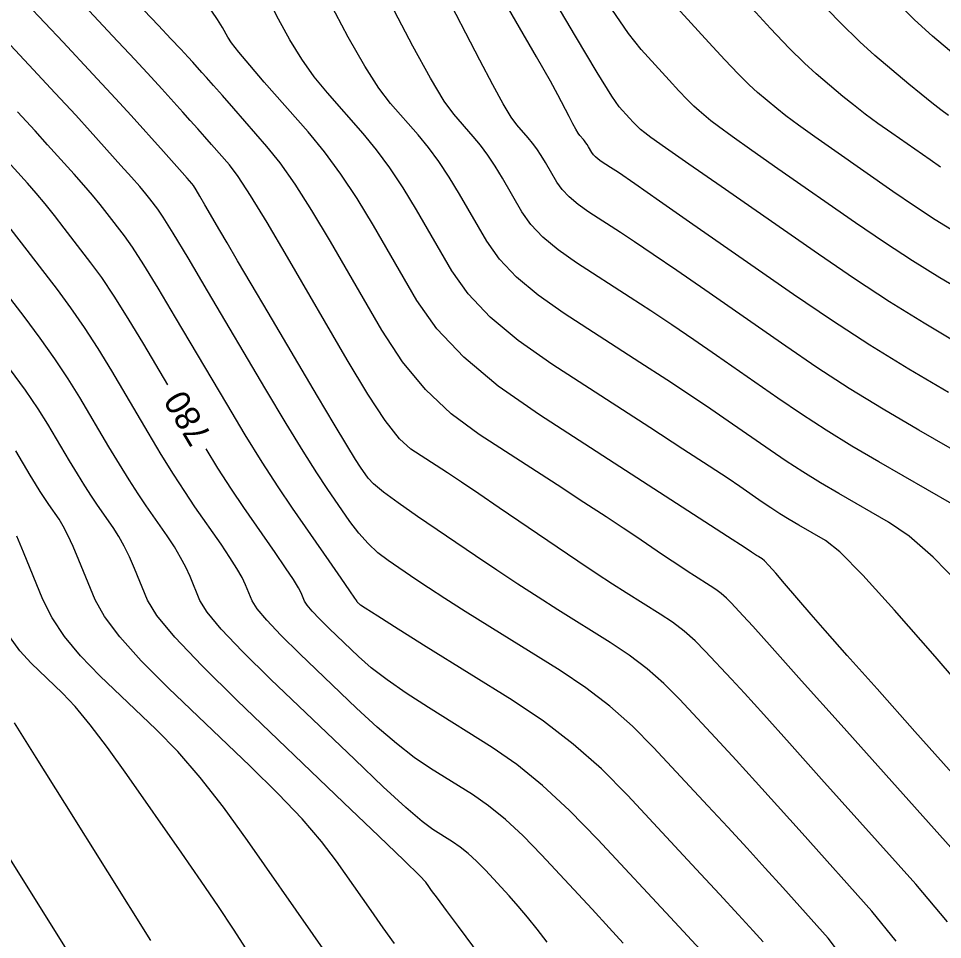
# Model space of a CAD drawing. Extents: x 2082232 to 2083549, y 592624 to 593832.
# Drawn here: x 2082485.39 to 2082511.4, y 593238.65 to 593264.58 of the extents above; entities that cross this region are included whole.
import ezdxf

# ---------------------------------------------------------------- set-up
doc = ezdxf.new("R2010")
doc.units = 0
doc.layers.add('DT_X_Contour_Major', color=7, linetype='Continuous')
doc.layers.add('DT_X_Contour_Minor', color=7, linetype='Continuous')

msp = doc.modelspace()

# ---------------------------------------------------------------- linework, layer by layer
at = {"layer": 'DT_X_Contour_Major'}
for points in [[(2082511.88, 593240.97), (2082508.547, 593244.695), (2082507.437, 593245.935), (2082506.608, 593246.86), (2082506.059, 593247.469), (2082505.791, 593247.764), (2082505.451, 593248.13), (2082505.318, 593248.263), (2082505.176, 593248.388), (2082505.025, 593248.504), (2082504.864, 593248.611), (2082504.422, 593248.887), (2082504.242, 593249.001), (2082504.032, 593249.139), (2082503.793, 593249.298), (2082503.523, 593249.48), (2082502.766, 593249.996), (2082502.415, 593250.231), (2082501.929, 593250.552), (2082501.308, 593250.957), (2082500.552, 593251.447), (2082498.357, 593252.866), (2082497.568, 593253.449), (2082496.85, 593254.133), (2082496.201, 593254.918), (2082495.622, 593255.805), (2082494.171, 593258.305), (2082493.651, 593259.175), (2082493.18, 593259.911), (2082492.757, 593260.512), (2082492.383, 593260.979), (2082491.448, 593262.044), (2082491.13, 593262.407), (2082490.874, 593262.697), (2082490.682, 593262.915), (2082490.554, 593263.059), (2082490.294, 593263.348), (2082490.161, 593263.493), (2082489.956, 593263.714), (2082489.678, 593264.011), (2082489.329, 593264.382), (2082488.301, 593265.473)], [(2082513.448, 593251.436), (2082510.733, 593252.993), (2082509.736, 593253.578), (2082508.779, 593254.166), (2082507.863, 593254.757), (2082506.988, 593255.35), (2082504.709, 593256.937), (2082503.919, 593257.484), (2082503.261, 593257.937), (2082502.733, 593258.294), (2082502.335, 593258.556), (2082501.45, 593259.128), (2082501.144, 593259.342), (2082500.891, 593259.554), (2082500.692, 593259.764), (2082500.545, 593259.973), (2082500.224, 593260.526), (2082500.103, 593260.725), (2082499.983, 593260.906), (2082499.862, 593261.07), (2082499.741, 593261.217), (2082499.418, 593261.585), (2082499.262, 593261.802), (2082499.038, 593262.177), (2082498.743, 593262.71), (2082498.38, 593263.402), (2082497.318, 593265.457)], [(2082511.347, 593260.397), (2082511.053, 593260.598), (2082509.974, 593261.349), (2082509.584, 593261.625), (2082509.225, 593261.89), (2082508.897, 593262.144), (2082508.599, 593262.386), (2082507.846, 593263.018), (2082507.515, 593263.318), (2082507.086, 593263.743), (2082506.56, 593264.294), (2082505.937, 593264.971)], [(2082489.592, 593254.263), (2082488.913, 593255.41), (2082488.474, 593256.138), (2082488.08, 593256.763), (2082487.731, 593257.285), (2082487.428, 593257.703), (2082486.678, 593258.679), (2082486.402, 593259.033), (2082486.137, 593259.36), (2082485.883, 593259.663), (2082485.64, 593259.94), (2082485.008, 593260.644)], [(2082504.582, 593238.374), (2082503.869, 593239.142), (2082501.701, 593241.47), (2082500.906, 593242.287), (2082500.145, 593242.991), (2082499.419, 593243.581), (2082498.728, 593244.058), (2082496.931, 593245.18), (2082496.302, 593245.585), (2082495.765, 593245.959), (2082495.319, 593246.302), (2082494.963, 593246.614), (2082494.137, 593247.405), (2082493.861, 593247.675), (2082493.654, 593247.894), (2082493.515, 593248.06), (2082493.445, 593248.175), (2082493.347, 593248.411), (2082493.274, 593248.548), (2082493.127, 593248.782), (2082492.907, 593249.113), (2082492.612, 593249.542), (2082491.73, 593250.814), (2082491.382, 593251.329), (2082491.002, 593251.92), (2082490.668, 593252.46)], [(2082494.298, 593237.916), (2082493.683, 593238.796), (2082491.837, 593241.441), (2082491.157, 593242.379), (2082490.501, 593243.213), (2082489.87, 593243.94), (2082489.263, 593244.562), (2082487.679, 593246.078), (2082487.133, 593246.639), (2082486.684, 593247.182), (2082486.332, 593247.709), (2082486.078, 593248.22), (2082485.527, 593249.559), (2082485.34, 593250.007)]]:
    msp.add_lwpolyline(points, dxfattribs=at)
at = {"layer": 'DT_X_Contour_Minor'}
for points in [[(2082514.571, 593242.685), (2082511.197, 593246.616), (2082510.055, 593247.926), (2082509.159, 593248.908), (2082508.51, 593249.561), (2082508.106, 593249.886), (2082507.358, 593250.315), (2082507.084, 593250.476), (2082506.82, 593250.638), (2082506.568, 593250.8), (2082506.327, 593250.964), (2082505.699, 593251.401), (2082505.364, 593251.628), (2082504.83, 593251.98), (2082504.096, 593252.459), (2082503.162, 593253.064), (2082500.407, 593254.845), (2082499.456, 593255.511), (2082498.67, 593256.17), (2082498.048, 593256.824), (2082497.591, 593257.472), (2082496.592, 593259.193), (2082496.217, 593259.812), (2082495.842, 593260.376), (2082495.466, 593260.886), (2082495.09, 593261.343), (2082494.086, 593262.488), (2082493.717, 593262.939), (2082493.365, 593263.435), (2082493.028, 593263.975), (2082492.707, 593264.559), (2082491.872, 593266.175)], [(2082511.569, 593254.052), (2082510.457, 593254.706), (2082509.359, 593255.384), (2082508.276, 593256.086), (2082507.208, 593256.812), (2082504.378, 593258.782), (2082503.438, 593259.436), (2082502.738, 593259.922), (2082502.278, 593260.239), (2082502.06, 593260.387), (2082501.797, 593260.556), (2082501.707, 593260.619), (2082501.632, 593260.682), (2082501.573, 593260.745), (2082501.529, 593260.806), (2082501.434, 593260.97), (2082501.398, 593261.029), (2082501.363, 593261.083), (2082501.327, 593261.131), (2082501.291, 593261.175), (2082501.196, 593261.284), (2082501.149, 593261.348), (2082501.083, 593261.459), (2082500.996, 593261.617), (2082500.888, 593261.822), (2082500.574, 593262.431), (2082500.364, 593262.813), (2082499.971, 593263.503), (2082499.395, 593264.502), (2082498.636, 593265.809)], [(2082511.825, 593255.442), (2082510.882, 593255.999), (2082509.915, 593256.601), (2082508.923, 593257.248), (2082507.908, 593257.941), (2082505.167, 593259.848), (2082504.262, 593260.479), (2082503.603, 593260.941), (2082503.189, 593261.233), (2082503.021, 593261.356), (2082502.899, 593261.458), (2082502.845, 593261.507), (2082502.776, 593261.575), (2082502.691, 593261.665), (2082502.59, 593261.774), (2082502.3, 593262.093), (2082502.091, 593262.394), (2082501.681, 593263.056), (2082501.07, 593264.08), (2082500.258, 593265.466)], [(2082511.777, 593258.555), (2082511.201, 593258.914), (2082510.61, 593259.299), (2082510.005, 593259.712), (2082508.372, 593260.849), (2082507.81, 593261.243), (2082507.351, 593261.574), (2082506.994, 593261.84), (2082506.74, 593262.043), (2082506.197, 593262.498), (2082505.958, 593262.714), (2082505.649, 593263.021), (2082505.27, 593263.418), (2082504.822, 593263.905), (2082503.531, 593265.326)], [(2082510.098, 593238.608), (2082509.416, 593239.447), (2082507.452, 593241.641), (2082506.755, 593242.418), (2082506.136, 593243.103), (2082505.594, 593243.697), (2082505.13, 593244.199), (2082503.997, 593245.417), (2082503.557, 593245.859), (2082503.084, 593246.273), (2082502.581, 593246.659), (2082502.046, 593247.017), (2082500.577, 593247.934), (2082500.019, 593248.286), (2082499.445, 593248.657), (2082498.856, 593249.046), (2082498.252, 593249.454), (2082496.622, 593250.564), (2082496.076, 593250.943), (2082495.663, 593251.248), (2082495.383, 593251.478), (2082495.234, 593251.634), (2082495.015, 593251.949), (2082494.878, 593252.163), (2082494.631, 593252.568), (2082494.275, 593253.163), (2082493.808, 593253.949), (2082492.418, 593256.3), (2082491.942, 593257.105), (2082491.557, 593257.758), (2082491.263, 593258.259), (2082491.059, 593258.607), (2082490.639, 593259.331), (2082490.497, 593259.573), (2082490.389, 593259.754), (2082490.314, 593259.874), (2082490.272, 593259.934), (2082490.203, 593260.012), (2082490.138, 593260.085), (2082489.994, 593260.246), (2082489.771, 593260.495), (2082489.468, 593260.832), (2082488.557, 593261.846), (2082488.117, 593262.329), (2082487.48, 593263.016), (2082486.645, 593263.908), (2082485.614, 593265.003)], [(2082513.769, 593240.998), (2082510.626, 593244.511), (2082509.56, 593245.704), (2082508.718, 593246.651), (2082508.1, 593247.349), (2082507.707, 593247.801), (2082506.957, 593248.674), (2082506.706, 593248.963), (2082506.518, 593249.176), (2082506.391, 593249.311), (2082506.325, 593249.369), (2082506.233, 593249.422), (2082506.2, 593249.442), (2082506.167, 593249.462), (2082506.136, 593249.482), (2082506.107, 593249.502), (2082506.029, 593249.555), (2082505.846, 593249.675), (2082505.353, 593249.995), (2082504.55, 593250.514), (2082503.438, 593251.234), (2082500.059, 593253.418), (2082498.893, 593254.233), (2082497.929, 593255.042), (2082497.167, 593255.844), (2082496.607, 593256.639), (2082495.382, 593258.749), (2082494.922, 593259.507), (2082494.462, 593260.199), (2082494.001, 593260.825), (2082493.54, 593261.385), (2082492.308, 593262.789), (2082491.898, 593263.263), (2082491.589, 593263.631), (2082491.383, 593263.893), (2082491.278, 593264.049), (2082491.136, 593264.325), (2082490.994, 593264.549), (2082490.674, 593265.017)], [(2082511.909, 593248.631), (2082511.136, 593249.414), (2082510.462, 593250.005), (2082509.887, 593250.403), (2082508.483, 593251.207), (2082507.968, 593251.51), (2082507.473, 593251.814), (2082506.999, 593252.119), (2082506.547, 593252.426), (2082505.369, 593253.246), (2082504.883, 593253.58), (2082504.307, 593253.966), (2082503.641, 593254.404), (2082502.886, 593254.895), (2082500.754, 593256.273), (2082500.019, 593256.788), (2082499.41, 593257.298), (2082498.929, 593257.804), (2082498.576, 593258.306), (2082497.803, 593259.637), (2082497.513, 593260.116), (2082497.222, 593260.553), (2082496.931, 593260.948), (2082496.64, 593261.301), (2082495.863, 593262.187), (2082495.537, 593262.616), (2082495.14, 593263.24), (2082494.673, 593264.057), (2082494.135, 593265.069)], [(2082511.576, 593261.849), (2082511.358, 593262.007), (2082511.1, 593262.207), (2082510.8, 593262.447), (2082510.459, 593262.73), (2082509.495, 593263.538), (2082509.071, 593263.922), (2082508.523, 593264.466), (2082507.85, 593265.171)], [(2082512.258, 593263.124), (2082511.118, 593264.08), (2082510.613, 593264.538), (2082509.953, 593265.194)], [(2082511.545, 593239.152), (2082510.648, 593240.208), (2082508, 593243.168), (2082507.096, 593244.176), (2082506.372, 593244.981), (2082505.827, 593245.583), (2082505.461, 593245.982), (2082504.724, 593246.773), (2082504.437, 593247.061), (2082504.13, 593247.33), (2082503.803, 593247.581), (2082503.455, 593247.814), (2082502.5, 593248.41), (2082502.11, 593248.658), (2082501.655, 593248.955), (2082501.137, 593249.3), (2082500.555, 593249.693), (2082498.918, 593250.808), (2082498.347, 593251.196), (2082497.862, 593251.523), (2082497.464, 593251.788), (2082497.151, 593251.993), (2082496.434, 593252.457), (2082496.119, 593252.744), (2082495.715, 593253.259), (2082495.221, 593254.002), (2082494.638, 593254.972), (2082492.961, 593257.861), (2082492.387, 593258.835), (2082491.924, 593259.593), (2082491.57, 593260.133), (2082491.327, 593260.456), (2082490.826, 593261.028), (2082490.634, 593261.246), (2082490.434, 593261.472), (2082490.226, 593261.705), (2082490.011, 593261.945), (2082489.426, 593262.597), (2082489.125, 593262.926), (2082488.661, 593263.426), (2082488.034, 593264.095), (2082487.245, 593264.934)], [(2082511.668, 593250.92), (2082509.608, 593252.1), (2082508.852, 593252.544), (2082508.126, 593252.99), (2082507.431, 593253.438), (2082506.767, 593253.888), (2082505.039, 593255.091), (2082504.401, 593255.532), (2082503.784, 593255.951), (2082503.187, 593256.349), (2082502.611, 593256.725), (2082501.102, 593257.701), (2082500.581, 593258.065), (2082500.151, 593258.426), (2082499.81, 593258.784), (2082499.56, 593259.139), (2082499.013, 593260.082), (2082498.808, 593260.42), (2082498.602, 593260.729), (2082498.397, 593261.009), (2082498.191, 593261.259), (2082497.641, 593261.886), (2082497.376, 593262.256), (2082496.992, 593262.895), (2082496.491, 593263.804), (2082495.872, 593264.982)], [(2082512.082, 593256.833), (2082511.33, 593257.277), (2082510.558, 593257.757), (2082509.767, 593258.274), (2082508.956, 593258.826), (2082506.769, 593260.349), (2082506.036, 593260.861), (2082505.477, 593261.257), (2082505.092, 593261.537), (2082504.88, 593261.699), (2082504.548, 593261.978), (2082504.402, 593262.11), (2082504.213, 593262.298), (2082503.981, 593262.541), (2082503.706, 593262.84), (2082502.915, 593263.71), (2082502.563, 593264.156), (2082502.097, 593264.842)], [(2082508.652, 593238.065), (2082508.183, 593238.685), (2082506.905, 593240.113), (2082506.414, 593240.659), (2082505.9, 593241.225), (2082505.361, 593241.811), (2082504.8, 593242.417), (2082503.27, 593244.06), (2082502.676, 593244.657), (2082502.038, 593245.216), (2082501.359, 593245.737), (2082500.637, 593246.22), (2082498.654, 593247.457), (2082497.967, 593247.888), (2082497.392, 593248.253), (2082496.929, 593248.552), (2082496.578, 593248.786), (2082495.792, 593249.321), (2082495.504, 593249.54), (2082495.229, 593249.796), (2082494.968, 593250.09), (2082494.719, 593250.42), (2082494.074, 593251.35), (2082493.785, 593251.785), (2082493.402, 593252.394), (2082492.926, 593253.176), (2082492.356, 593254.132), (2082490.712, 593256.913), (2082490.162, 593257.838), (2082489.745, 593258.531), (2082489.462, 593258.99), (2082489.312, 593259.215), (2082489.09, 593259.504), (2082488.976, 593259.644), (2082488.802, 593259.847), (2082488.568, 593260.114), (2082488.274, 593260.443), (2082487.409, 593261.407), (2082487.001, 593261.855), (2082486.424, 593262.477), (2082485.68, 593263.272), (2082484.769, 593264.241)], [(2082506.358, 593238.586), (2082506.073, 593238.9), (2082505.663, 593239.346), (2082505.129, 593239.924), (2082504.469, 593240.634), (2082502.544, 593242.703), (2082501.798, 593243.453), (2082501.007, 593244.149), (2082500.17, 593244.794), (2082499.287, 593245.386), (2082496.87, 593246.894), (2082496.075, 593247.391), (2082495.501, 593247.752), (2082495.148, 593247.976), (2082495.017, 593248.064), (2082494.963, 593248.115), (2082494.945, 593248.133), (2082494.932, 593248.147), (2082494.923, 593248.158), (2082494.918, 593248.166), (2082494.912, 593248.181), (2082494.861, 593248.256), (2082494.715, 593248.468), (2082494.472, 593248.819), (2082494.133, 593249.307), (2082493.102, 593250.793), (2082492.696, 593251.394), (2082492.252, 593252.085), (2082491.77, 593252.863), (2082491.25, 593253.73), (2082489.813, 593256.161), (2082489.318, 593256.988), (2082488.913, 593257.647), (2082488.597, 593258.137), (2082488.37, 593258.459), (2082487.884, 593259.092), (2082487.689, 593259.338), (2082487.47, 593259.604), (2082487.226, 593259.888), (2082486.957, 593260.192), (2082486.208, 593261.025), (2082485.855, 593261.413), (2082485.356, 593261.952)], [(2082502.41, 593238.551), (2082502.021, 593238.984), (2082501.537, 593239.51), (2082500.117, 593241.035), (2082499.595, 593241.57), (2082499.097, 593242.031), (2082498.621, 593242.418), (2082498.169, 593242.731), (2082496.991, 593243.465), (2082496.53, 593243.778), (2082496.029, 593244.165), (2082495.489, 593244.627), (2082494.909, 593245.164), (2082493.311, 593246.694), (2082492.777, 593247.217), (2082492.376, 593247.64), (2082492.108, 593247.962), (2082491.971, 593248.184), (2082491.783, 593248.64), (2082491.687, 593248.84), (2082491.54, 593249.095), (2082491.342, 593249.408), (2082491.092, 593249.776), (2082490.357, 593250.835), (2082490.068, 593251.263), (2082489.752, 593251.755), (2082489.409, 593252.309), (2082489.038, 593252.927), (2082488.014, 593254.658), (2082487.631, 593255.288), (2082487.248, 593255.88), (2082486.866, 593256.433), (2082486.486, 593256.947), (2082485.472, 593258.267), (2082485.115, 593258.727)], [(2082500.27, 593238.58), (2082499.993, 593238.944), (2082499.723, 593239.282), (2082499.46, 593239.593), (2082499.205, 593239.877), (2082498.532, 593240.6), (2082498.285, 593240.854), (2082498.049, 593241.072), (2082497.824, 593241.255), (2082497.609, 593241.403), (2082497.052, 593241.751), (2082496.758, 593241.972), (2082496.294, 593242.372), (2082495.659, 593242.953), (2082494.855, 593243.714), (2082492.485, 593245.983), (2082491.694, 593246.759), (2082491.099, 593247.386), (2082490.7, 593247.864), (2082490.498, 593248.193), (2082490.219, 593248.87), (2082490.101, 593249.132), (2082489.953, 593249.409), (2082489.776, 593249.702), (2082489.571, 593250.011), (2082488.985, 593250.856), (2082488.754, 593251.198), (2082488.502, 593251.59), (2082488.228, 593252.032), (2082487.932, 593252.525), (2082487.115, 593253.907), (2082486.787, 593254.438), (2082486.416, 593254.996), (2082486.001, 593255.58), (2082485.544, 593256.191), (2082484.265, 593257.854)], [(2082498.797, 593237.639), (2082497.775, 593239.015), (2082497.436, 593239.472), (2082497.184, 593239.812), (2082497.02, 593240.035), (2082496.943, 593240.141), (2082496.855, 593240.267), (2082496.686, 593240.443), (2082496.244, 593240.876), (2082495.529, 593241.565), (2082494.543, 593242.512), (2082491.547, 593245.379), (2082490.547, 593246.361), (2082489.794, 593247.159), (2082489.286, 593247.773), (2082489.024, 593248.202), (2082488.655, 593249.099), (2082488.514, 593249.424), (2082488.366, 593249.723), (2082488.211, 593249.997), (2082488.05, 593250.246), (2082487.612, 593250.877), (2082487.44, 593251.132), (2082487.252, 593251.425), (2082487.047, 593251.756), (2082486.826, 593252.124), (2082486.216, 593253.156), (2082485.943, 593253.588), (2082485.583, 593254.112), (2082485.136, 593254.728)], [(2082495.97, 593238.537), (2082495.659, 593238.976), (2082495.313, 593239.468), (2082494.346, 593240.854), (2082493.921, 593241.411), (2082493.372, 593242.044), (2082492.7, 593242.753), (2082491.903, 593243.537), (2082489.613, 593245.728), (2082488.84, 593246.5), (2082488.239, 593247.171), (2082487.809, 593247.741), (2082487.551, 593248.211), (2082487.091, 593249.329), (2082486.927, 593249.715), (2082486.778, 593250.036), (2082486.646, 593250.291), (2082486.529, 593250.48), (2082486.24, 593250.897), (2082486.126, 593251.066), (2082486.001, 593251.26), (2082485.866, 593251.479), (2082485.72, 593251.722), (2082485.317, 593252.404)], [(2082491.795, 593238.385), (2082491.439, 593238.943), (2082491.018, 593239.579), (2082490.534, 593240.292), (2082489.987, 593241.083), (2082488.442, 593243.296), (2082487.894, 593244.061), (2082487.408, 593244.698), (2082486.985, 593245.207), (2082486.624, 593245.586), (2082485.745, 593246.428), (2082485.427, 593246.774), (2082485.135, 593247.181)], [(2082489.118, 593238.621), (2082486.696, 593242.49), (2082485.887, 593243.779), (2082485.277, 593244.748)], [(2082487.02, 593237.932), (2082484.972, 593241.204)]]:
    msp.add_lwpolyline(points, dxfattribs=at)

# ---------------------------------------------------------------- texts
at = {"layer": 'DT_X_Contour_Major'}
msp.add_text('780', height=0.7, rotation=120.8279, dxfattribs=at).set_placement((2082490.848, 593252.833))

doc.saveas('drawing.dxf')
